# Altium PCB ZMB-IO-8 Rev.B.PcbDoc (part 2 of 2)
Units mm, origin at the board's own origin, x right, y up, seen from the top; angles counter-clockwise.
Board outline 164 x 122 mm, 8 copper layers (Top Layer, L2, L3, L4, L5, L6, L7, Bottom Layer), stack 1.966 mm thick; 31 components, 171 nets, 626 pads, 99 vias.
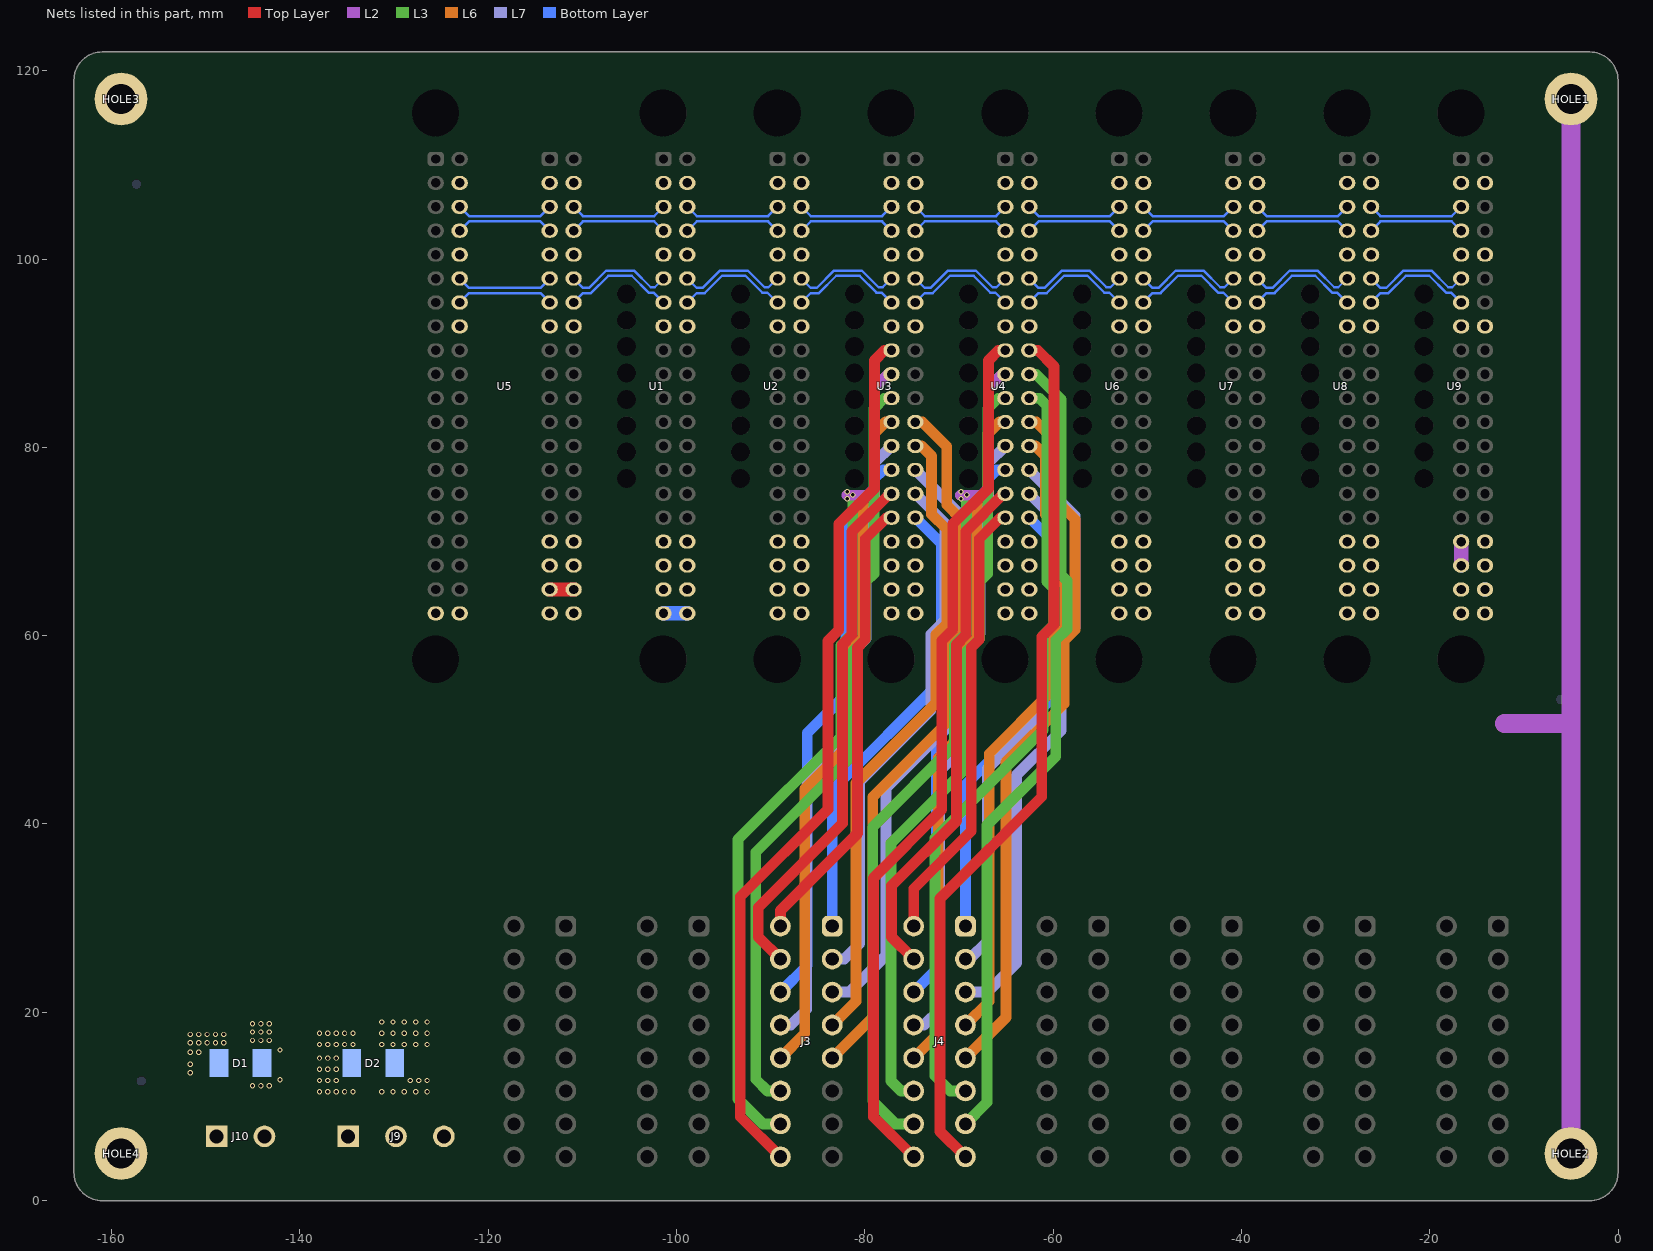
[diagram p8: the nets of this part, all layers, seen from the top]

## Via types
v1: diameter 0.559, hole 0.356, Top Layer to Bottom Layer, tented both sides, 99 vias

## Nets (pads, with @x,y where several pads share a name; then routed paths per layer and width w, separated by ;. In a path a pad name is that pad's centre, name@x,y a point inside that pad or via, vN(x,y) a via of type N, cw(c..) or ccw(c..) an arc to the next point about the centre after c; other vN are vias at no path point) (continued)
DO4: J3.9 U3.24 | length 75.7
  L6 w1.143: J3.9@-83.462,15.15 -79.162,19.45 -79.162,42.879 -70.917,51.124 -70.917,59.491 -69.78,60.628 -69.78,72.376 -71.304,73.9 -71.304,80.1 -73.895,82.69 U3.24@-74.647,82.69
DO5: J3.7 U3.26 | length 68.3
  L6 w1.143: J3.7@-83.462,18.65 -80.948,21.164 -80.948,44.344 -72.447,52.845 -72.447,60.116 -71.304,61.259 -71.304,71.295 -72.912,72.903 -72.912,79.086 -73.977,80.15 U3.26@-74.647,80.15
DO6: J3.5 U3.28 | length 64.4
  L7 w1.143: J3.5@-83.462,22.15 -81.63,22.15 -77.75,26.03 -77.75,43.83 -71.013,50.567 -71.013,59.575 -69.578,61.01 -69.578,72.558 U3.28@-74.63,77.61
DO7: J3.3 U3.30 | length 56.4
  L7 w1.143: J3.3@-83.462,25.65 -82.194,25.65 -80.539,27.305 -80.539,44.482 -72.99,52.032 -72.99,60.156 -71.495,61.651 -71.495,71.935 U3.30@-74.63,75.07
DO8: J3.1 U3.32 | length 49.3
  Bottom Layer w1.143: J3.1@-83.462,29.15 -83.462,43.588 -71.856,55.194 -71.856,69.756 U3.32@-74.63,72.53
DO9: J3.16 U3.17 | length 94.5
  Top Layer w1.143: J3.16@-88.962,4.65 -93.223,8.912 -93.223,32.271 -83.921,41.573 -83.921,59.447 -82.762,60.605 -82.762,71.85 -78.973,75.639 -78.973,89.239 -77.902,90.31 U3.17@-77.17,90.31
DO10: J3.14 U3.19 | length 91.3
  L2 w1.143: -81.93,74.904 -79.737,74.904 -78.969,75.672 -78.969,86.344 -77.543,87.77 U3.19@-77.17,87.77
  L3 w1.143: J3.14@-88.962,8.15 -90.826,8.15 -93.466,10.79 -93.466,38.367 -82.566,49.268 -82.566,58.952 -81.293,60.225 -81.293,74.435 -81.788,74.93
  other v1: -81.879,74.549 -81.269,74.955 -81.879,75.285
DO11: J3.12 U3.21 | length 81.9
  L3 w1.143: J3.12@-88.962,11.65 -90.344,11.65 -91.587,12.893 -91.587,36.988 -81.22,47.355 -81.22,58.395 -79.891,59.723 -79.891,65.719 -79.035,66.576 -79.035,84.125 -77.93,85.23 U3.21@-77.17,85.23
DO12: J3.10 U3.23 | length 72.8
  L6 w1.143: J3.10@-88.962,15.15 -86.374,17.737 -86.374,43.715 -81.372,48.717 -81.372,58.801 -80.246,59.927 -80.246,73.896 -79.009,75.133 -79.009,81.485 -77.803,82.69 U3.23@-77.17,82.69
DO13: J3.8 U3.25 | length 67
  L7 w1.143: J3.8@-88.962,18.65 -87.863,18.65 -86.18,20.333 -86.18,44.621 -81.077,49.724 -81.077,58.509 -79.88,59.705 -79.88,73.926 -78.943,74.863 -78.943,78.377 U3.25@-77.17,80.15
DO14: J3.6 U3.27 | length 60.9
  Bottom Layer w1.143: J3.6@-88.962,22.15 -86.106,25.006 -86.106,49.654 -82.007,53.753 -82.007,72.136 -78.994,75.149 -78.994,76.698 -78.082,77.61 U3.27@-77.17,77.61
DO15: J3.4 U3.29 | length 56.4
  Top Layer w1.143: J3.4@-88.962,25.65 -91.32,28.009 -91.32,31.12 -82.373,40.068 -82.373,59.076 -81.352,60.096 -81.352,71.079 -77.361,75.07 U3.29@-77.17,75.07
DO16: J3.2 U3.31 | length 48.6
  Top Layer w1.143: J3.2@-88.962,29.15 -88.962,30.812 -80.788,38.986 -80.788,58.753 -79.953,59.587 -79.953,70.288 -77.711,72.53 -77.701,72.53 U3.31@-77.17,72.53
DO17: J4.15 U4.18 | length 93.4
  Top Layer w1.143: J4.15@-69.312,4.65 -72.009,7.347 -72.009,32.089 -61.205,42.893 -61.205,59.879 -59.909,61.175 -59.909,88.591 -61.627,90.31 U4.18@-62.53,90.31
DO18: J4.13 U4.20 | length 86.2
  L3 w1.143: J4.13@-69.312,8.15 -67.012,10.45 -67.012,39.88 -59.712,47.18 -59.712,59.51 -58.503,60.718 -58.503,65.82 -59.131,66.448 -59.131,85.08 -61.821,87.77 U4.20@-62.547,87.77
DO19: J4.11 U4.22 | length 82.8
  L3 w1.143: J4.11@-69.312,11.65 -70.934,11.65 -72.542,13.259 -72.542,38.49 -61.058,49.974 -61.058,60.067 -59.901,61.225 -59.901,65.003 -60.667,65.769 -60.667,84.45 -61.447,85.23 U4.22@-62.547,85.23
DO20: J4.9 U4.24 | length 74.8
  L6 w1.143: J4.9@-69.312,15.15 -65.012,19.45 -65.012,46.574 -58.817,52.769 -58.817,59.491 -57.68,60.628 -57.68,72.376 -59.204,73.9 -59.204,80.1 -61.795,82.69 U4.24@-62.547,82.69
DO21: J4.7 U4.26 | length 67.5
  L6 w1.143: J4.7@-69.312,18.65 -66.798,21.164 -66.798,47.455 -60.347,53.906 -60.347,60.116 -59.204,61.259 -59.204,71.295 -60.812,72.903 -60.812,79.086 -61.877,80.15 U4.26@-62.547,80.15
DO22: J4.5 U4.28 | length 63.7
  L7 w1.143: J4.5@-69.312,22.15 -66.976,22.15 -63.888,25.238 -63.888,45.193 -59.139,49.942 -59.139,59.401 -57.649,60.891 -57.649,72.729 U4.28@-62.53,77.61
DO23: J4.3 U4.30 | length 55
  L7 w1.143: J4.3@-69.312,25.65 -68.894,25.65 -67.003,27.541 -67.003,45.843 -61.106,51.741 -61.106,59.821 -59.453,61.473 -59.453,71.993 U4.30@-62.53,75.07
DO24: J4.1 U4.32 | length 48.5
  Bottom Layer w1.143: J4.1@-69.312,29.15 -69.312,44.171 -59.756,53.727 -59.756,69.756 U4.32@-62.53,72.53
DO25: J4.16 U4.17 | length 93.7
  Top Layer w1.143: J4.16@-74.812,4.65 -79.073,8.912 -79.073,34.278 -71.821,41.531 -71.821,59.447 -70.662,60.606 -70.662,71.85 -66.873,75.639 -66.873,89.239 -65.802,90.31 U4.17@-65.07,90.31
DO26: J4.14 U4.19 | length 90.4
  L2 w1.143: -69.83,74.904 -67.637,74.904 -66.869,75.672 -66.869,86.344 -65.443,87.77 U4.19@-65.07,87.77
  L3 w1.143: J4.14@-74.812,8.15 -76.73,8.15 -79.165,10.585 -79.165,39.682 -70.466,48.38 -70.466,58.952 -69.193,60.225 -69.193,74.435 -69.688,74.93
  other v1: -69.779,74.549 -69.169,74.955 -69.779,75.285
DO27: J4.12 U4.21 | length 80.8
  L3 w1.143: J4.12@-74.812,11.65 -76.166,11.65 -77.216,12.7 -77.216,37.947 -69.12,46.044 -69.12,58.395 -67.791,59.723 -67.791,65.719 -66.935,66.576 -66.935,84.125 -65.83,85.23 U4.21@-65.07,85.23
DO28: J4.10 U4.23 | length 71.9
  L6 w1.143: J4.10@-74.812,15.15 -72.204,17.758 -72.204,47.043 -69.272,49.975 -69.272,58.801 -68.146,59.927 -68.146,73.896 -66.909,75.133 -66.909,81.485 -65.703,82.69 U4.23@-65.07,82.69
DO29: J4.8 U4.25 | length 66.2
  L7 w1.143: J4.8@-74.812,18.65 -73.713,18.65 -72.03,20.333 -72.03,45.621 -68.977,48.675 -68.977,59.075 -67.78,60.272 -67.78,73.926 -66.843,74.863 -66.843,78.377 U4.25@-65.07,80.15
DO30: J4.6 U4.27 | length 60
  Bottom Layer w1.143: J4.6@-74.812,22.15 -72.39,24.572 -72.39,49.079 -69.907,51.562 -69.907,72.136 -66.894,75.149 -66.894,76.698 -65.982,77.61 U4.27@-65.07,77.61
DO31: J4.4 U4.29 | length 55.5
  Top Layer w1.143: J4.4@-74.812,25.65 -77.17,28.009 -77.17,33.432 -70.273,40.329 -70.273,59.076 -69.252,60.096 -69.252,71.079 -65.261,75.07 U4.29@-65.07,75.07
DO32: J4.2 U4.31 | length 47.7
  Top Layer w1.143: J4.2@-74.812,29.15 -74.812,33.123 -68.688,39.247 -68.688,58.753 -67.853,59.587 -67.853,70.288 -65.611,72.53 U4.31@-65.07,72.53
E_24V: D1.2 J10.1 U5.B36 U5.B37 U5.B38 | length 2.5
  Top Layer w1.524: U5.B37@-113.47,64.91 U5.B38@-110.93,64.91
  other v1: -151.638,13.589 -151.638,14.478 -151.638,15.748 -150.749,15.748 -151.638,16.764 -150.749,16.764 -149.86,16.764 -148.971,16.764 -148.082,16.764 -151.638,17.653 -150.749,17.653 -149.86,17.653 -148.971,17.653 -148.082,17.653
E_GND: D1.1 J10.2 U5.B33 U5.B34 U5.B35
  other v1: -145.034,12.192 -144.145,12.192 -143.256,12.192 -142.113,12.827 -142.113,16.002 -145.034,17.018 -144.145,17.018 -143.256,17.018 -145.034,17.907 -144.145,17.907 -143.256,17.907 -145.034,18.796 -144.145,18.796 -143.256,18.796
EARTH: HOLE1.1 HOLE2.1 HOLE3.1 HOLE4.1 J9.3 U1.39 U1.40 U2.39 U2.40 U3.39 U3.40 U4.39 U4.40 U5.A39 U5.A40 U5.B39 U5.B40 U6.39 U6.40 U7.39 U7.40 U8.39 U8.40 U9.39 U9.40 | length 121.6
  L2 w2.032: -12.065,50.673 -5,50.673 ; HOLE2.1@-5,5 -5,50.673 ; HOLE1.1@-5,117 -5,50.673
  Bottom Layer w1.524: U1.39@-101.387,62.37 U1.40@-98.847,62.37
"GND ETC": U1.3 U1.4 U1.9 U1.10 U1.15 U1.16 U2.3 U2.4 U2.9 U2.10 U2.15 U2.16 U3.3 U3.4 U3.9 U3.10 U3.15 U3.16 U4.3 U4.4 U4.9 U4.10 U4.15 U4.16 U5.A4 U5.A10 U5.A16 U5.B3 U5.B4 U5.B9 U5.B10 U5.B15 U5.B16 U6.3 U6.4 U6.9 U6.10 U6.15 U6.16 U7.3 U7.4 U7.9 U7.10 U7.15 U7.16 U8.3 U8.4 U8.9 U8.10 U8.15 U8.16 U9.3 U9.4 U9.9 U9.10 U9.15 U9.16
M_24V: D2.2 J9.1 U1.36 U1.37 U1.38 U2.36 U2.37 U2.38 U3.36 U3.37 U3.38 U4.36 U4.37 U4.38 U6.36 U6.37 U6.38 U7.36 U7.37 U7.38 U8.36 U8.37 U8.38 U9.36 U9.37 U9.38 | length 0
  other v1: -137.922,11.557 -137.033,11.557 -136.144,11.557 -135.255,11.557 -134.366,11.557 -137.922,12.751 -137.033,12.751 -136.144,12.751 -137.922,13.945 -137.033,13.945 -136.144,13.945 -137.922,15.138 -137.033,15.138 -136.144,15.138 -137.922,16.586 -137.033,16.586 -136.144,16.586 -135.255,16.586 -134.366,16.586 -137.922,17.78 -137.033,17.78 -136.144,17.78 -135.255,17.78 -134.366,17.78
M_GND: D2.1 J9.2 U1.33 U1.34 U1.35 U2.33 U2.34 U2.35 U3.33 U3.34 U3.35 U4.33 U4.34 U4.35 U6.33 U6.34 U6.35 U7.33 U7.34 U7.35 U8.33 U8.34 U8.35 U9.33 U9.34 U9.35 | length 2.5
  L2 w1.524: U9.35@-16.67,67.45 U9.33@-16.67,69.99
  other v1: -131.318,11.557 -130.112,11.557 -128.905,11.557 -127.698,11.557 -126.492,11.557 -128.27,12.751 -127.381,12.751 -126.492,12.751 -131.318,16.586 -130.112,16.586 -128.905,16.586 -127.698,16.586 -126.492,16.586 -131.318,17.78 -130.112,17.78 -128.905,17.78 -127.698,17.78 -126.492,17.78 -131.318,18.974 -130.112,18.974 -128.905,18.974 -127.698,18.974 -126.492,18.974
NetU1_5: U1.5 U5.B6 | length 10.4
  Bottom Layer w0.254: U5.B6@-110.93,105.55 -109.939,104.559 -102.361,104.559 U1.5@-101.37,105.55
NetU1_6: U1.6 U2.5 | length 10.4
  Bottom Layer w0.254: U1.6@-98.847,105.55 -97.856,104.56 -90.277,104.56 U2.5@-89.287,105.55
NetU1_7: U1.7 U5.B8 | length 10.4
  Bottom Layer w0.254: U5.B8@-110.93,103.01 -109.939,104.001 -102.361,104.001 U1.7@-101.37,103.01
NetU1_8: U1.8 U2.7 | length 10.4
  Bottom Layer w0.254: U1.8@-98.847,103.01 -97.856,104.001 -90.277,104.001 U2.7@-89.287,103.01
NetU1_11: U1.11 U5.B12 | length 11.8
  Bottom Layer w0.254: U5.B12@-110.93,97.93 -109.939,96.939 -109.313,96.939 -107.472,98.781 -104.521,98.781 -102.743,97.003 -102.315,97.003 U1.11@-101.387,97.93
NetU1_12: U1.12 U2.11 | length 11.8
  Bottom Layer w0.254: U1.12@-98.847,97.93 -97.856,96.94 -97.23,96.94 -95.389,98.781 -92.438,98.781 -90.66,97.003 -90.231,97.003 U2.11@-89.304,97.931
NetU1_13: U1.13 U5.B14 | length 11.9
  Bottom Layer w0.254: U5.B14@-110.93,95.39 -109.939,96.381 -109.081,96.381 -107.24,98.222 -104.752,98.222 -102.974,96.444 -102.44,96.444 U1.13@-101.387,95.39
NetU1_14: U1.14 U2.13 | length 11.9
  Bottom Layer w0.254: U1.14@-98.847,95.39 -97.856,96.381 -96.998,96.381 -95.157,98.222 -92.669,98.222 -90.891,96.444 -90.357,96.444 U2.13@-89.304,95.391
NetU2_6: U2.6 U3.5 | length 10.4
  Bottom Layer w0.254: U2.6@-86.73,105.55 -85.739,104.559 -78.161,104.559 U3.5@-77.17,105.55
NetU2_8: U2.8 U3.7 | length 10.4
  Bottom Layer w0.254: U2.8@-86.73,103.01 -85.739,104.001 -78.16,104.001 U3.7@-77.17,103.01
NetU2_12: U2.12 U3.11 | length 11.8
  Bottom Layer w0.254: U2.12@-86.73,97.93 -85.739,96.939 -85.113,96.939 -83.272,98.781 -80.321,98.781 -78.543,97.003 -78.115,97.003 U3.11@-77.187,97.93
NetU2_14: U2.14 U3.13 | length 11.9
  Bottom Layer w0.254: U2.14@-86.73,95.39 -85.739,96.381 -84.881,96.381 -83.04,98.222 -80.552,98.222 -78.774,96.444 -78.24,96.444 U3.13@-77.187,95.39
NetU3_6: U3.6 U4.5 | length 10.4
  Bottom Layer w0.254: U3.6@-74.63,105.55 -73.639,104.559 -66.061,104.559 U4.5@-65.07,105.55
NetU3_8: U3.8 U4.7 | length 10.4
  Bottom Layer w0.254: U3.8@-74.63,103.01 -73.639,104.001 -66.06,104.001 U4.7@-65.07,103.01
NetU3_12: U3.12 U4.11 | length 11.8
  Bottom Layer w0.254: U3.12@-74.63,97.93 -73.639,96.939 -73.013,96.939 -71.172,98.781 -68.221,98.781 -66.443,97.003 -66.015,97.003 U4.11@-65.087,97.93
NetU3_14: U3.14 U4.13 | length 11.9
  Bottom Layer w0.254: U3.14@-74.63,95.39 -73.639,96.381 -72.781,96.381 -70.94,98.222 -68.452,98.222 -66.674,96.444 -66.14,96.444 U4.13@-65.087,95.39
NetU5_A6: U5.A6 U5.B5 | length 10.4
  Bottom Layer w0.254: U5.A6@-123.03,105.55 -122.039,104.559 -114.461,104.559 U5.B5@-113.47,105.55
NetU5_A8: U5.A8 U5.B7 | length 10.4
  Bottom Layer w0.254: U5.A8@-123.03,103.01 -122.039,104.001 -114.461,104.001 U5.B7@-113.47,103.01
NetU5_A12: U5.A12 U5.B11 | length 10.4
  Bottom Layer w0.254: U5.A12@-123.03,97.93 -122.039,96.939 -114.461,96.939 U5.B11@-113.47,97.93
NetU5_A14: U5.A14 U5.B13 | length 10.4
  Bottom Layer w0.254: U5.A14@-123.03,95.39 -122.039,96.381 -114.461,96.381 U5.B13@-113.47,95.39
NetU6_6: U6.6 U7.5 | length 10.4
  Bottom Layer w0.254: U6.6@-50.43,105.55 -49.439,104.559 -41.861,104.559 U7.5@-40.87,105.55
NetU6_8: U6.8 U7.7 | length 10.4
  Bottom Layer w0.254: U6.8@-50.43,103.01 -49.439,104.001 -41.86,104.001 U7.7@-40.87,103.01
NetU6_12: U6.12 U7.11 | length 11.8
  Bottom Layer w0.254: U6.12@-50.43,97.93 -49.439,96.939 -48.813,96.939 -46.972,98.781 -44.021,98.781 -42.243,97.003 -41.815,97.003 U7.11@-40.887,97.93
NetU6_14: U6.14 U7.13 | length 11.9
  Bottom Layer w0.254: U6.14@-50.43,95.39 -49.439,96.381 -48.581,96.381 -46.74,98.222 -44.252,98.222 -42.474,96.444 -41.94,96.444 U7.13@-40.887,95.39
NetU7_6: U7.6 U8.5 | length 10.4
  Bottom Layer w0.254: U7.6@-38.33,105.55 -37.339,104.559 -29.761,104.559 U8.5@-28.77,105.55
NetU7_8: U7.8 U8.7 | length 10.4
  Bottom Layer w0.254: U7.8@-38.33,103.01 -37.339,104.001 -29.76,104.001 U8.7@-28.77,103.01
NetU7_12: U7.12 U8.11 | length 11.8
  Bottom Layer w0.254: U7.12@-38.33,97.93 -37.339,96.939 -36.713,96.939 -34.872,98.781 -31.921,98.781 -30.143,97.003 -29.715,97.003 U8.11@-28.787,97.93
NetU7_14: U7.14 U8.13 | length 11.9
  Bottom Layer w0.254: U7.14@-38.33,95.39 -37.339,96.381 -36.481,96.381 -34.64,98.222 -32.152,98.222 -30.374,96.444 -29.84,96.444 U8.13@-28.787,95.39
NetU8_6: U8.6 U9.5 | length 10.4
  Bottom Layer w0.254: U8.6@-26.23,105.55 -25.239,104.559 -17.661,104.559 U9.5@-16.67,105.55
NetU8_8: U8.8 U9.7 | length 10.4
  Bottom Layer w0.254: U8.8@-26.23,103.01 -25.239,104.001 -17.66,104.001 U9.7@-16.67,103.01
NetU8_12: U8.12 U9.11 | length 11.8
  Bottom Layer w0.254: U8.12@-26.23,97.93 -25.239,96.939 -24.613,96.939 -22.772,98.781 -19.821,98.781 -18.043,97.003 -17.615,97.003 U9.11@-16.687,97.93
NetU8_14: U8.14 U9.13 | length 11.9
  Bottom Layer w0.254: U8.14@-26.23,95.39 -25.239,96.381 -24.381,96.381 -22.54,98.222 -20.052,98.222 -18.274,96.444 -17.74,96.444 U9.13@-16.687,95.39
RX1+: U4.12 U6.11 | length 11.8
  Bottom Layer w0.254: U4.12@-62.53,97.93 -61.539,96.939 -60.913,96.939 -59.072,98.781 -56.121,98.781 -54.343,97.003 -53.915,97.003 U6.11@-52.987,97.93
RX1-: U4.14 U6.13 | length 11.9
  Bottom Layer w0.254: U4.14@-62.53,95.39 -61.539,96.381 -60.681,96.381 -58.84,98.222 -56.352,98.222 -54.574,96.444 -54.04,96.444 U6.13@-52.987,95.39
TX1+: U4.6 U6.5 | length 10.4
  Bottom Layer w0.254: U4.6@-62.53,105.55 -61.539,104.559 -53.961,104.559 U6.5@-52.97,105.55
TX1-: U4.8 U6.7 | length 10.4
  Bottom Layer w0.254: U4.8@-62.53,103.01 -61.539,104.001 -53.96,104.001 U6.7@-52.97,103.01
pads on no net: MARK5.0 MARK6.0 MARK7.0 U1. U2. U3. U4. U5. U5.A1 U5.A3 U5.A5 U5.A7 U5.A9 U5.A11 U5.A13 U5.A15 U5.A17 U5.A18 U5.A19 U5.A20 U5.A21 U5.A22 U5.A23 U5.A24 U5.A25 U5.A26 U5.A27 U5.A28 U5.A29 U5.A30 U5.A31 U5.A32 U5.A33 U5.A34 U5.A35 U5.A36 U5.A37 U5.A38 U5.B17 U5.B18 U5.B19 U5.B20 U5.B21 U5.B22 U5.B23 U5.B24 U5.B25 U5.B26 U5.B27 U5.B28 U5.B29 U5.B30 U5.B31 U5.B32 U6. U7. U8. U9. U9.6 U9.8 U9.12 U9.14

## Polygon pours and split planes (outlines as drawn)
EARTH on L2 "NONET_L-01_P-001" (solid, remove dead copper, pour order 15): -159.893,48.387 -160.528,49.022 -160.528,61.214 -158.622,63.12 -4.7,63.12 -4.318,62.738 -4.318,50.165 -6.096,48.387
"GND ETC" on L2 "NONET_L-01_P-001" (solid, remove dead copper, pour order 17): -129.159,93.091 -128.168,92.1 -12.294,92.1 -11.684,92.71 -11.684,110.871 -12.827,112.014 -128.651,112.014 -129.159,111.506
EARTH on L2 "NONET_L-01_P-001" (solid, remove dead copper, pour order 23): -7.8,2.212 -7.112,1.524 -3.091,1.524 -2.202,2.413 -2.202,118.491 -3.511,119.8 -6.862,119.8 -7.8,118.862
EARTH on L2 "NONET_L-01_P-001" (solid, remove dead copper, pour order 16): -125.864,7.74 -125.476,8.128 -122.682,8.128 -122.174,7.62 -122.174,2.667 -124.206,0.635 -160.02,0.635 -161.798,2.413 -161.798,118.491 -160.489,119.8 -157.138,119.8 -156.2,118.862 -156.2,4.816 -154.559,3.175 -126.855,3.175 -125.864,4.166
E_24V on L7 "NONET_L-01_P-001" (solid, remove dead copper, pour order 19): -140.335,26.924 -146.685,20.574 -146.685,13.843 -147.574,12.954 -151.384,12.954 -152.146,13.716 -152.146,35.941 -132.842,55.245 -132.842,69.977 -131.699,71.12 -109.728,71.12 -109.093,70.485 -109.093,58.039 -140.208,26.924
"GND ETC" on L7 "NONET_L-01_P-001" (solid, remove dead copper, pour order 26): -129.159,93.091 -128.168,92.1 -12.294,92.1 -11.684,92.71 -11.684,110.871 -12.827,112.014 -128.651,112.014 -129.159,111.506
E_24V on Top Layer "NONET_L-01_P-001" (solid, remove dead copper, pour order 22): -146.685,20.447 -146.685,13.843 -147.574,12.954 -151.384,12.954 -152.146,13.716 -152.146,35.941 -132.842,55.245 -132.842,69.977 -131.699,71.12 -110.744,71.12 -110.109,70.485 -110.109,64.77 -110.744,64.135 -115.443,64.135 -115.951,63.627 -115.951,51.181
"GND ETC" on Top Layer "NONET_L-01_P-001" (solid, remove dead copper, pour order 28): -129.159,93.091 -128.168,92.1 -12.294,92.1 -11.684,92.71 -11.684,110.871 -12.827,112.014 -128.651,112.014 -129.159,111.506
M_24V on L5 "NONET_L-01_P-001" (solid, remove dead copper, pour order 27): -139.573,10.541 -138.938,9.906 -127,9.906 -122.047,14.859 -8.509,14.859 -6.223,17.145 -6.223,72.898 -8.255,74.93 -75.9,74.93 -92.887,74.914 -104.41,74.914 -105.788,73.536 -105.788,60.492 -113.956,52.324 -139.192,52.324 -139.573,51.943
"GND ETC" on L5 "NONET_L-01_P-001" (solid, remove dead copper, pour order 25): -129.159,93.091 -128.168,92.1 -12.294,92.1 -11.684,92.71 -11.684,110.871 -12.827,112.014 -128.651,112.014 -129.159,111.506
E_GND on Bottom Layer "NONET_L-01_P-001" (solid, remove dead copper, pour order 18): -150.749,19.304 -150.368,18.923 -147.447,18.923 -146.304,17.78 -146.304,6.35 -145.631,5.677 -142.024,5.677 -141.351,6.35 -141.351,24.003 -110.109,55.245 -110.109,71.12 -110.871,71.882 -131.953,71.882 -133.731,70.104 -133.731,55.562 -150.749,38.544
E_GND on L6 "NONET_L-01_P-001" (solid, remove dead copper, pour order 24): -150.749,21.209 -146.304,16.764 -146.304,6.35 -145.631,5.677 -142.024,5.677 -141.351,6.35 -141.351,24.003 -110.109,55.245 -110.109,71.12 -110.871,71.882 -131.953,71.882 -133.731,70.104 -133.731,55.562 -150.749,38.544
M_GND on L4 "NONET_L-01_P-001" (solid, remove dead copper, pour order 20): -139.446,9.652 -138.557,8.763 -133.477,8.763 -132.969,8.255 -132.969,6.096 -132.55,5.677 -128.016,5.677 -127.889,5.842 -127.889,8.509 -125.73,10.668 -121.539,14.859 -8.509,14.859 -6.223,17.145 -6.223,72.898 -8.255,74.93 -75.9,74.93 -92.887,74.914 -104.41,74.914 -105.788,73.536 -105.788,60.492 -113.956,52.324 -139.192,52.324 -139.446,52.07

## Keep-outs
Keep-Out Layer:
  lines w0.1: -3,122 cw(c-3,119) 0,119 0,3 cw(c-3,3) -3,0 -161,0 cw(c-161,3) -164,3 -164,119 cw(c-161,119) -161,122 -2.981,122
  lines w0.102: -164,0 -161,0 ; -164,119 -164,122 ; -161,122 -164,122 ; -3,122 0,122 ; -164,122 -164,122 ; -164,122 -164,122
  lines w0.152: -3.001,0 0,0 0,3.001

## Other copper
L2:
  region net EARTH: -125.857,4.953 -125.857,6.985 -125.476,7.366 -123.317,7.366 -122.936,6.985 -122.936,4.953 -123.317,4.572 -125.476,4.572
Bottom Layer:
  region net E_GND: -145.631,5.677 -146.304,6.35 -146.304,17.653 -145.923,18.034 -141.986,18.034 -141.351,17.399 -141.351,6.35 -142.024,5.677
  region net M_GND: -132.905,17.843 -132.905,19.367 -132.715,19.558 -126.238,19.558 -125.857,19.177 -125.857,11.356 -128.413,8.8 -128.413,5.908 -128.644,5.677 -132.804,5.677 -132.969,5.842 -132.969,17.78
  region net M_24V: -138.303,19.304 -138.049,19.558 -133.731,19.558 -133.493,19.32 -133.493,5.908 -133.724,5.677 -138.077,5.677 -138.303,5.903
  region net E_24V: -152.146,17.653 -151.765,18.034 -148.082,18.034 -147.694,17.646 -147.694,5.677 -151.346,5.677 -152.146,6.477

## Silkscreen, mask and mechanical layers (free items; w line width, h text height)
Top Overlay:
  rectangle: -159.797,50.927 -153.797,56.927
  lines w0.127: -160.443,36.619 -119.792,36.619 ; -160.443,38.276 -119.792,38.276 ; -160.443,39.933 -119.792,39.933 ; -160.443,41.59 -119.792,41.59 ; -160.443,43.247 -119.792,43.247 ; -160.443,44.904 -119.792,44.904 ; -160.443,46.561 -119.792,46.561 ; -160.443,48.218 -119.792,48.218 ; -157.672,34.962 -157.672,49.875 ; -153.873,34.962 -153.873,49.875 ; -150.277,34.962 -150.277,49.875 ; -146.084,34.962 -146.084,49.875 ; -141.527,34.962 -141.527,49.875 ; -138.342,34.962 -138.342,49.875 ; -135.553,34.962 -135.553,49.875 ; -132.969,34.962 -132.969,49.875 ; -130.131,34.962 -130.131,49.875 ; -126.673,34.962 -126.673,49.875 ; -123.449,34.962 -123.449,49.875 ; -160.443,34.962 -160.443,49.875 -119.792,49.875 -119.792,34.962 -160.443,34.962
  text "EtherCAT Coupler" at -150.989,50.937 h2.54
  text "Module1" at -106.203,49.108 h3.05
  text "Module2" at -94.415,49.108 h3.05
  text "Module3" at -82.325,49.108 h3.05
  text "Module4" at -70.238,49.108 h3.05
  text "Module5" at -58.036,49.108 h3.05
  text "Module6" at -45.946,49.108 h3.05
  text "Module7" at -33.798,49.108 h3.05
  text "Module8" at -21.665,49.108 h3.05
  text "PIN" at -160.071,48.554 h1.78
  text "MT" at -157.143,48.554 h1.78
  text "DI" at -153.433,48.554 h1.78
  text "DO" at -149.248,48.554 h1.78
  text "AO" at -145.79,48.554 h1.78
  text "AI" at -141.217,48.554 h1.78
  text "PIN" at -137.964,48.554 h1.78
  text "MT" at -135.197,48.554 h1.78
  text "DI" at -132.526,48.554 h1.78
  text "DO" at -129.747,48.554 h1.78
  text "AO" at -126.427,48.554 h1.78
  text "AI" at -123.066,48.554 h1.78
  text "2" at -160.067,46.903 h1.78
  text "DI16" at -153.415,46.901 h1.78
  text "DO16" at -149.915,46.901 h1.78
  text "Lat" at -135.23,46.915 h1.78
  text "DI8" at -132.558,46.923 h1.78
  text "DO8" at -129.779,46.922 h1.78
  text "AO8" at -126.459,46.922 h1.78
  text "+AI8" at -123.098,46.923 h1.78
  text "EncC" at -157.124,46.899 h1.78
  text "AGND" at -145.772,46.899 h1.78
  text "-AI8" at -141.199,46.9 h1.78
  text "1" at -137.651,46.898 h1.78
  text "4" at -160.065,45.268 h1.78
  text "5V" at -135.23,45.258 h1.78
  text "DI7" at -132.558,45.25 h1.78
  text "DO7" at -129.779,45.263 h1.78
  text "AO7" at -126.459,45.263 h1.78
  text "+AI7" at -123.098,45.25 h1.78
  text "GND" at -157.124,45.228 h1.78
  text "DI15" at -153.415,45.234 h1.78
  text "DO15" at -149.915,45.241 h1.78
  text "AGND" at -145.772,45.24 h1.78
  text "-AI7" at -141.199,45.228 h1.78
  text "3" at -137.65,45.23 h1.78
  text "6" at -160.065,43.6 h1.78
  text "D2" at -135.23,43.601 h1.78
  text "DI6" at -132.558,43.61 h1.78
  text "DO6" at -129.779,43.604 h1.78
  text "AO6" at -126.459,43.604 h1.78
  text "+AI6" at -123.098,43.61 h1.78
  text "DO14" at -149.915,43.58 h1.78
  text "AGND" at -145.772,43.58 h1.78
  text "-AI6" at -141.199,43.587 h1.78
  text "5" at -137.65,43.579 h1.78
  text "EncB" at -157.124,43.557 h1.78
  text "DI14" at -153.415,43.567 h1.78
  text "8" at -160.067,41.933 h1.78
  text "7" at -137.651,41.944 h1.78
  text "D1" at -135.23,41.944 h1.78
  text "DI5" at -132.558,41.936 h1.78
  text "DO5" at -129.779,41.945 h1.78
  text "AO5" at -126.459,41.945 h1.78
  text "+AI5" at -123.098,41.936 h1.78
  text "EncA" at -157.124,41.903 h1.78
  text "DI13" at -153.415,41.917 h1.78
  text "DO13" at -149.915,41.92 h1.78
  text "AGND" at -145.772,41.92 h1.78
  text "-AI5" at -141.199,41.913 h1.78
  text "9" at -137.65,40.276 h1.78
  text "B2" at -135.23,40.282 h1.78
  text "DI4" at -132.558,40.278 h1.78
  text "DO4" at -129.779,40.286 h1.78
  text "AO4" at -126.459,40.286 h1.78
  text "+AI4" at -123.098,40.278 h1.78
  text "10" at -160.067,40.26 h1.78
  text "B2" at -157.124,40.248 h1.78
  text "DI12" at -153.415,40.25 h1.78
  text "DO12" at -149.915,40.259 h1.78
  text "AGND" at -145.772,40.26 h1.78
  text "-AI4" at -141.199,40.256 h1.78
  text "B1" at -135.23,38.625 h1.78
  text "DI3" at -132.558,38.638 h1.78
  text "DO3" at -129.779,38.626 h1.78
  text "AO3" at -126.459,38.626 h1.78
  text "+AI3" at -123.098,38.638 h1.78
  text "12" at -160.067,38.604 h1.78
  text "DI11" at -153.415,38.6 h1.78
  text "DO11" at -149.915,38.598 h1.78
  text "AGND" at -145.772,38.601 h1.78
  text "-AI3" at -141.199,38.615 h1.78
  text "11" at -137.651,38.62 h1.78
  text "B1" at -157.124,38.594 h1.78
  text "14" at -160.067,36.947 h1.78
  text "DI10" at -153.415,36.95 h1.78
  text "13" at -137.651,36.947 h1.78
  text "A2" at -135.23,36.963 h1.78
  text "DI2" at -132.558,36.964 h1.78
  text "DO2" at -129.779,36.967 h1.78
  text "AO2" at -126.459,36.967 h1.78
  text "+AI2" at -123.098,36.964 h1.78
  text "A2" at -157.124,36.935 h1.78
  text "DO10" at -149.915,36.938 h1.78
  text "AGND" at -145.772,36.941 h1.78
  text "-AI2" at -141.199,36.941 h1.78
  text "A1" at -135.23,35.306 h1.78
  text "DI1" at -132.558,35.306 h1.78
  text "DO1" at -129.779,35.308 h1.78
  text "AO1" at -126.459,35.308 h1.78
  text "+AI1" at -123.098,35.306 h1.78
  text "16" at -160.067,35.274 h1.78
  text "A1" at -157.124,35.281 h1.78
  text "DI9" at -153.415,35.283 h1.78
  text "DO9" at -149.915,35.277 h1.78
  text "AGND" at -145.772,35.281 h1.78
  text "-AI1" at -141.199,35.284 h1.78
  text "15" at -137.651,35.274 h1.78
  text "4" at -73.525,33.137 h5.08
  text "5" at -59.011,33.137 h5.08
  text "7" at -30.676,33.137 h5.08
  text "2" at -101.792,33.088 h5.08
  text "3" at -87.608,33.088 h5.08
  text "6" at -44.953,33.088 h5.08
  text "8" at -16.4,33.088 h5.08
  text "1" at -115.319,33.074 h5.08
  text "2" at -121.211,28.448 h2.03
  text "1" at -108.839,28.448 h2.03
  text "2" at -107.061,28.448 h2.03
  text "1" at -94.689,28.448 h2.03
  text "2" at -92.911,28.448 h2.03
  text "1" at -80.539,28.448 h2.03
  text "2" at -78.761,28.448 h2.03
  text "1" at -66.389,28.448 h2.03
  text "2" at -64.611,28.448 h2.03
  text "1" at -52.24,28.448 h2.03
  text "2" at -50.462,28.448 h2.03
  text "1" at -38.09,28.448 h2.03
  text "2" at -36.312,28.448 h2.03
  text "1" at -23.94,28.448 h2.03
  text "2" at -22.162,28.448 h2.03
  text "1" at -9.79,28.448 h2.03
  text "ZMB-IO-8" at -145.796,25.654 h3.81
  text "250917 Rev.B" at -147.812,22.606 h3.3
  text "P/N:134010103951" at -151.053,19.431 h3.3
  text "System" at -133.316,13.855 h2.54
  text "EtherCAT" at -150.711,13.595 h2.54
  text "GND" at -145.542,11.43 h1.78
  text "GND" at -131.572,11.43 h1.78
  text "24V" at -150.368,11.411 h1.78
  text "24V" at -136.144,11.411 h1.78
  text "EARTH" at -127.127,11.411 h1.78
  text "16" at -118.417,0.658 h2.03
  text "15" at -112.903,0.658 h2.03
  text "16" at -104.267,0.658 h2.03
  text "15" at -98.753,0.658 h2.03
  text "16" at -90.117,0.658 h2.03
  text "15" at -84.603,0.658 h2.03
  text "16" at -75.967,0.658 h2.03
  text "15" at -70.453,0.658 h2.03
  text "16" at -61.817,0.658 h2.03
  text "15" at -56.304,0.658 h2.03
  text "16" at -47.668,0.658 h2.03
  text "15" at -42.154,0.658 h2.03
  text "16" at -33.518,0.658 h2.03
  text "15" at -28.004,0.658 h2.03
  text "16" at -19.368,0.658 h2.03
  text "15" at -13.854,0.658 h2.03
Bottom Overlay:
  rectangle: -157.988,50.927 -151.988,56.927
  region: -157.608,100.614 -159.068,103.535 -160.529,100.614
  region: -159.968,93.883 -159.968,100.614 -158.16,100.614 -158.16,93.883 -158.465,93.883 -158.465,100.137 -159.644,100.137 -159.644,94.518 -158.465,94.518 -158.465,93.883
  text "SMT B" at -159.644,94.518 h2.29 r270
Mechanical 1:
  lines w0.1: -179,122 -172,122 -173,123 ; -161,122 ccw(c-161,119) -164,119 -164,3 ccw(c-161,3) -161,0 -3,0 ccw(c-3,3) 0,3 0,119 ccw(c-3,119) -3,122 ; -161,122 cw(c-161,125) -164,125 -164,241 cw(c-161,241) -161,244 -3,244 cw(c-3,241) 0,241 0,125 cw(c-3,125) -3,122 ; -161,122 -3,122 ; -161,122 -3,122
  text "F" at -159.245,224.549 h12.7
  text "V-CUT" at -183.182,121.659 h0.76
  text "F" at -159.245,97.224 h12.7
Drill Drawing:
  drawing of 1731 lines, arcs and shapes, not listed
  text "Symbol" at -171.513,301.688 h1.83
  text "Count" at -158.664,301.688 h1.83
  text "Hole Size" at -143.682,301.688 h1.83
  text "Hole Length" at -114.481,301.688 h1.83
  text "Plated" at -92.49,301.688 h1.83
  text "Hole Type" at -79.641,301.688 h1.83
  text "Drill Layer Pair" at -61.003,301.688 h1.83
  text "Via/Pad" at -22.914,301.688 h1.83
  text "Pad Shape" at -7.932,301.688 h1.83
  text "Hole Tolerance (+)" at 11.011,301.688 h1.83
  text "Hole Tolerance (-)" at 44.885,301.688 h1.83
  text "4" at -158.664,297.878 h1.52
  text "125.98mil (3.200mm)" at -143.682,297.878 h1.52
  text "-" at -114.481,297.878 h1.52
  text "PTH" at -92.49,297.878 h1.52
  text "Round" at -79.641,297.878 h1.52
  text "Top Layer - Bottom Layer" at -61.003,297.878 h1.52
  text "Pad" at -22.914,297.878 h1.52
  text "Rounded" at -7.932,297.878 h1.52
  text "5" at -158.664,294.068 h1.52
  text "59.06mil (1.500mm)" at -143.682,294.068 h1.52
  text "-" at -114.481,294.068 h1.52
  text "PTH" at -92.49,294.068 h1.52
  text "Round" at -79.641,294.068 h1.52
  text "Top Layer - Bottom Layer" at -61.003,294.068 h1.52
  text "Pad" at -22.914,294.068 h1.52
  text "(Mixed)" at -7.932,294.068 h1.52
  text "18" at -158.664,290.258 h1.52
  text "196.85mil (5.000mm)" at -143.682,290.258 h1.52
  text "-" at -114.481,290.258 h1.52
  text "NPTH" at -92.49,290.258 h1.52
  text "Round" at -79.641,290.258 h1.52
  text "Top Layer - Bottom Layer" at -61.003,290.258 h1.52
  text "Pad" at -22.914,290.258 h1.52
  text "Rounded" at -7.932,290.258 h1.52
  text "64" at -158.664,286.448 h1.52
  text "78.74mil (2.000mm)" at -143.682,286.448 h1.52
  text "-" at -114.481,286.448 h1.52
  text "NPTH" at -92.49,286.448 h1.52
  text "Round" at -79.641,286.448 h1.52
  text "Top Layer - Bottom Layer" at -61.003,286.448 h1.52
  text "Pad" at -22.914,286.448 h1.52
  text "Rounded" at -7.932,286.448 h1.52
  text "99" at -158.664,282.638 h1.52
  text "14.00mil (0.356mm)" at -143.682,282.638 h1.52
  text "-" at -114.481,282.638 h1.52
  text "PTH" at -92.49,282.638 h1.52
  text "Round" at -79.641,282.638 h1.52
  text "Top Layer - Bottom Layer" at -61.003,282.638 h1.52
  text "Via" at -22.914,282.638 h1.52
  text "Rounded" at -7.932,282.638 h1.52
  text "128" at -158.664,278.828 h1.52
  text "55.12mil (1.400mm)" at -143.682,278.828 h1.52
  text "-" at -114.481,278.828 h1.52
  text "PTH" at -92.49,278.828 h1.52
  text "Round" at -79.641,278.828 h1.52
  text "Top Layer - Bottom Layer" at -61.003,278.828 h1.52
  text "Pad" at -22.914,278.828 h1.52
  text "(Mixed)" at -7.932,278.828 h1.52
  text "400" at -158.664,275.018 h1.52
  text "39.37mil (1.000mm)" at -143.682,275.018 h1.52
  text "-" at -114.481,275.018 h1.52
  text "PTH" at -92.49,275.018 h1.52
  text "Round" at -79.641,275.018 h1.52
  text "Top Layer - Bottom Layer" at -61.003,275.018 h1.52
  text "Pad" at -22.914,275.018 h1.52
  text "(Mixed)" at -7.932,275.018 h1.52
  text "718 Total" at -158.664,271.209 h1.52
  text "PCB加工工艺要求 V2508a" at 85.702,195.74 h7.11
  text "mm x" at 57.588,191.11 h2.54
  text "mm" at 73.082,191.11 h2.54
  text "±0.15mm" at 78.691,190.924 h2.54
  text "244" at 49.079,190.881 h2.54
  text "164" at 64.573,190.881 h2.54
  text "（IPC-600、IPC-6011/12）最新版本" at 108.718,190.856 h2.54
  text "IPC-Ⅱ" at 152.406,190.83 h2.54
  text "IPC-Ⅲ" at 165.106,190.83 h2.54
  text "尺寸" at 35.533,190.402 h5.08
  text "验收标准" at 92.175,190.402 h5.08
  text "S1000H" at 71.253,186.944 h2.03
  text "S1000-2 / S1000-2M / TU768" at 104.273,186.944 h2.03
  text "FR4" at 55.943,186.821 h2.03
  text "FR4" at 88.933,186.821 h2.03
  text "(" at 61.322,185.826 h1.91
  text ")" at 78.467,185.826 h1.91
  text "(" at 94.342,185.826 h1.91
  text ")" at 128.378,185.826 h1.91
  text "其他：" at 164.852,185.776 h2.54
  text "RO4350B" at 137.801,185.71 h2.54
  text "M6" at 154.946,185.71 h2.54
  text "可选型号" at 61.881,185.674 h2.54
  text "可选型号" at 94.901,185.674 h2.54
  text "板材" at 35.497,185.317 h5.08
  text "TG150" at 54.74,184.954 h2.03
  text "TG170" at 87.73,184.954 h2.03
  text "IT158TC" at 71.126,184.912 h2.03
  text "IT180A / IT180ATC" at 104.4,184.912 h2.03
  text "单面" at 54.235,180.696 h2.54
  text "2" at 72.015,180.696 h2.54
  text "4" at 89.795,180.696 h2.54
  text "6" at 107.575,180.696 h2.54
  text "8" at 125.355,180.696 h2.54
  text "10" at 143.135,180.696 h2.54
  text "12" at 160.915,180.696 h2.54
  text "板层" at 35.497,180.231 h5.08
  text "0.4mm" at 54.235,175.616 h2.54
  text "0.6mm" at 68.205,175.616 h2.54
  text "0.8mm" at 82.175,175.616 h2.54
  text "1.0mm" at 96.145,175.616 h2.54
  text "1.2mm" at 110.115,175.616 h2.54
  text "1.4mm" at 124.085,175.616 h2.54
  text "1.6mm" at 138.055,175.616 h2.54
  text "1.8mm" at 152.025,175.616 h2.54
  text "2.0mm" at 165.995,175.616 h2.54
  text "板厚" at 35.497,175.146 h5.08
  text "0.5OZ" at 70.237,170.536 h2.54
  text "1OZ" at 82.937,170.536 h2.54
  text "2OZ" at 95.637,170.536 h2.54
  text "0.5OZ" at 141.23,170.536 h2.54
  text "1OZ" at 155.454,170.536 h2.54
  text "2OZ" at 168.154,170.536 h2.54
  text "外层" at 53.907,170.18 h4.06
  text "内层" at 123.577,170.184 h4.06
  text "完成铜厚" at 35.494,170.02 h5.08
  text "白色" at 162.82,165.456 h2.54
  text "绿色" at 65.665,165.202 h2.54
  text "黑色" at 83.445,165.202 h2.54
  text "红色" at 101.225,165.202 h2.54
  text "蓝色" at 119.005,165.202 h2.54
  text "（亮光）" at 51.251,165.136 h4.06
  text "阻焊颜色" at 35.494,164.955 h5.08
  text "丝印颜色" at 132.649,164.941 h5.08
  text "沉镍金: 镍厚≥3um，金厚≥0.05um" at 58.202,160.416 h2.54
  text "电镀镍金: 镍厚≥3um，金厚≥0.05um" at 99.209,160.416 h2.54
  text "无铅喷锡" at 143.135,160.376 h2.54
  text "光板" at 158.375,160.376 h2.54
  text "沉银" at 169.043,160.376 h2.54
  text "表面处理" at 35.494,159.844 h5.08
  text "HDI" at 154.266,155.355 h2.54
  text "金手指" at 58.202,155.232 h2.54
  text "金手指: 镍厚≥5um，金厚≥0.76um" at 58.202,155.232 h2.54
  text "按键镀硬金: 镍厚≥5um，金厚≥0.76um" at 104.362,155.215 h2.54
  text "特殊工艺" at 35.494,152.752 h5.08
  text "翘曲度≤0.3%" at 154.54,151.206 h2.54
  text "半孔工艺: 孔径公差+/-0.076mm,锣板后单元板两边剩余半孔目视应均匀" at 58.02,151.105 h2.54
  text "阻焊塞孔，但双面开窗除外" at 58.045,146.295 h2.54
  text "不塞孔" at 92.208,146.304 h2.54
  text "树脂塞孔+电镀填平" at 107.31,146.304 h2.54
  text "树脂塞孔" at 134.336,146.304 h2.54
  text "电镀填平" at 151.862,146.313 h2.54
  text "塞孔方式" at 35.497,145.878 h5.08
  text "无V-CUT、无邮票孔" at 95.668,141.271 h2.54
  text "邮票孔" at 81.048,141.247 h2.54
  text "拼板:" at 54.997,141.224 h2.54
  text "V-CUT" at 65.919,141.224 h2.54
  text "非拼板" at 136.531,141.224 h2.54
  text "拼板方式" at 35.494,140.818 h5.08
  text "Gerber输出：英制、相对零点、抑制前导零、精度2:5" at 36.328,136.398 h3.05
  text "副边" at 158.629,135.255 h2.03
  text "NC Drill输出：英制、相对零点、抑制前导零、精度2:4" at 36.328,132.842 h3.05
  text "其他说明" at 35.439,128.219 h5.08
  text "桥连处不能添加铜皮" at 152.279,126.111 h2.03
  text "1." at 35.439,124.968 h3.05
  text "*.GM1 层为外形铣边；若存在工艺副边，请在副边上增加整块平衡铜，" at 38.741,124.968 h3.05
  text "禁止使用方块状、点状图形，防机器误识别。但若存在类似右图所示的桥连处，禁止添加平衡铜" at 38.614,122.047 h3.05
  text "2." at 35.437,118.872 h3.05
  text "请用供应商UL认证号，阻燃等级，CTI等级，生产周期替换板上的UR标识，且保持其位置、方向一致," at 38.741,118.872 h3.05
  text "若板内无，可在工艺副边添加; 禁止添加文件中不存在的元素，包括供应商LOGO、无铅、光学基准点等" at 38.741,115.579 h3.05
  text "R" at 165.513,113.17 h0.64
  text "3." at 35.439,112.268 h3.05
  text "若焊盘开窗与丝印油冲突，焊盘处需将丝印油掏开，不允许上焊盘" at 38.741,112.268 h3.05
  text "94V-0" at 167.291,111.76 h1.17
  text "标识样式>>>" at 148.215,110.744 h2.54
  text "CTI>=175" at 163.328,109.601 h2.2
  text "4." at 35.439,108.839 h3.05
  text "若存在单元板的器件丝印延伸至其他单元板时，需将延伸的部分切除" at 38.614,108.839 h3.05
  text "5." at 35.439,105.41 h3.05
  text "若存在6X6或5X5mm丝印白油块，为我司激光打标用，需完整及平整；若无则忽略" at 38.741,105.41 h3.05
  text "6." at 35.312,101.981 h3.05
  text "若存在V-CUT，无特别说明时，须为双面V-CUT，角度30（+-5°），余量按以下表格执行" at 38.741,101.981 h3.05
  text "PCB厚度（mm）" at 49.689,97.536 h3.05
  text "筋厚" at 41.18,97.155 h3.05
  text "（余量）" at 39.91,94.107 h3.05
  text "0.6" at 49.689,93.98 h3.05
  text "0.8" at 55.775,93.98 h3.05
  text "1" at 63.301,93.98 h3.05
  text "1.2" at 67.977,93.98 h3.05
  text "1.6" at 74.073,93.98 h3.05
  text "2" at 81.312,93.98 h3.05
  text "2.5" at 86.25,93.98 h3.05
  text "3" at 93.504,93.98 h3.05
  text "0.16" at 48.93,90.487 h3.05
  text "0.2" at 55.788,90.487 h3.05
  text "0.3" at 61.884,90.487 h3.05
  text "0.3" at 67.875,90.487 h3.05
  text "0.4" at 73.984,90.487 h3.05
  text "0.5" at 80.176,90.487 h3.05
  text "0.5" at 86.268,90.487 h3.05
  text "最小值" at 39.783,90.424 h3.05
  text "0.5" at 92.335,90.424 h3.05
  text "0.32" at 48.941,86.995 h3.05
  text "0.4" at 55.781,86.995 h3.05
  text "0.45" at 61.119,86.995 h3.05
  text "0.5" at 67.868,86.995 h3.05
  text "0.6" at 74.047,86.995 h3.05
  text "0.7" at 80.184,86.995 h3.05
  text "0.8" at 86.273,86.995 h3.05
  text "0.8" at 92.364,86.995 h3.05
  text "最大值" at 39.783,86.868 h3.05
  text "7." at 35.439,82.55 h3.05
  text "PCB做完后，请高温烘烤进行应力释放，再整平（或重物压板烘烤），防止翘曲" at 38.741,82.55 h3.05
  text "符合无铅和ROHS2.0环保标准" at 38.614,79.121 h3.05
  text "8." at 35.439,78.994 h3.05
  text "实心填充才是勾选状态；若下表与钻孔表有冲突，以公差精度高的为准" at 67.053,75.298 h3.05
  text "特殊孔径公差要求:" at 38.741,75.184 h3.05
  text "9." at 35.439,75.057 h3.05
  text "Select" at 39.503,71.866 h1.02
  text "Hole Size" at 48.409,71.866 h1.02
  text "Plated" at 60.363,71.866 h1.02
  text "Tolerance (+)" at 65.634,71.866 h1.02
  text "Tolerance (-)" at 77.078,71.866 h1.02
  text "Select" at 106.803,71.866 h1.02
  text "Hole Size" at 118.249,71.866 h1.02
  text "Plated" at 130.203,71.866 h1.02
  text "Tolerance (+)" at 135.474,71.866 h1.02
  text "Tolerance (-)" at 146.918,71.866 h1.02
  text "适用范围" at 89.622,71.607 h2.29
  text "适用范围" at 159.462,71.607 h2.29
  text "0.6mm" at 49.282,68.58 h1.02
  text "NPTH" at 60.561,68.58 h1.02
  text "0.05 mm" at 67.316,68.58 h1.02
  text "0 mm" at 80.143,68.58 h1.02
  text "1.5/1.55/2.25mm" at 115.068,68.58 h1.78
  text "NPTH" at 130.147,68.58 h1.78
  text "0.05 mm" at 137.222,68.58 h1.78
  text "0.05 mm" at 148.877,68.58 h1.78
  text "核心板连接器" at 88.079,68.498 h2.03
  text "导光柱" at 160.534,68.326 h2.03
  text "0.8mm" at 49.282,64.774 h1.02
  text "NPTH" at 60.561,64.774 h1.02
  text "0.1 mm" at 67.316,64.774 h1.02
  text "0 mm" at 80.143,64.774 h1.02
  text "1.5mm" at 118.107,64.774 h1.78
  text "NPTH" at 130.147,64.774 h1.78
  text "0 mm" at 138.921,64.774 h1.78
  text "0.1 mm" at 148.728,64.774 h1.78
  text "核心板连接器" at 88.079,64.7 h2.03
  text "导光柱" at 160.534,64.52 h2.03
  text "0.6mm" at 49.282,60.968 h1.02
  text "PTH" at 61.069,60.968 h1.02
  text "0.05 mm" at 67.316,60.968 h1.02
  text "0.05 mm" at 79.381,60.968 h1.02
  text "1.5mm" at 118.107,60.968 h1.78
  text "NPTH" at 130.147,60.968 h1.78
  text "0.05 mm" at 137.222,60.968 h1.78
  text "0 mm" at 149.984,60.968 h1.78
  text "压接针脚" at 89.793,60.86 h2.03
  text "导光柱" at 160.534,60.714 h2.03
  text "10." at 35.014,56.252 h3.05
  text "叠层如下，叠层顺序见*.EXTREP文件 (可用记事本打开)" at 39.376,54.356 h3.05
  text "TOP" at 74.397,50.673 h1.91
  text "<=50 (+-5 OHM) ; >50 (+-10%)" at 121.647,48.793 h1.91
  text "公差：" at 114.789,48.666 h3.05
  text "PREPREG" at 45.83,48.062 h1.91
  text "阻抗控制表" at 93.097,48.006 h5.59
  text "L2" at 75.444,45.631 h1.91
  text "单端" at 125.279,44.171 h3.05
  text "差分" at 152.965,44.145 h3.05
  text "CORE" at 45.853,41.91 h1.91
  text "阻抗" at 159.569,40.869 h3.05
  text "层" at 96.196,40.742 h3.05
  text "参考层" at 105.34,40.742 h3.05
  text "线宽/间距" at 143.186,40.742 h3.05
  text "阻抗" at 132.518,40.589 h3.05
  text "L3" at 75.444,40.424 h1.91
  text "线宽" at 118.506,40.395 h3.05
  text "(OHM)" at 158.426,37.567 h1.91
  text "(mil)" at 118.421,37.541 h1.91
  text "(mil)" at 146.107,37.541 h1.91
  text "(OHM)" at 131.248,37.44 h1.91
  text "PREPREG" at 45.599,35.052 h1.91
  text "8" at 95.002,33.528 h1.91
  text "7" at 107.194,33.528 h1.91
  text "100" at 159.95,33.503 h1.91
  text "10/12" at 144.583,33.477 h1.91
  text "L4" at 75.399,33.058 h1.91
  text "CORE" at 45.83,28.207 h1.91
  text "L5" at 75.444,23.66 h1.91
  text "PREPREG" at 45.726,21.844 h1.91
  text "L6" at 75.49,16.129 h1.91
  text "CORE" at 45.853,14.478 h1.91
  text "L7" at 75.444,10.795 h1.91
  text "注意：1、单端线宽不允许调大（共面除外）" at 92.635,10.132 h3.05
  text "PREPREG" at 45.83,8.346 h1.91
  text "2、出货时包装内需附上阻抗测试报告书" at 100.971,6.553 h3.05
  text "BOT" at 74.297,5.956 h1.91

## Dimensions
0,241 to -164,241 on Drill Drawing
-161,244 to -161,0 on Drill Drawing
